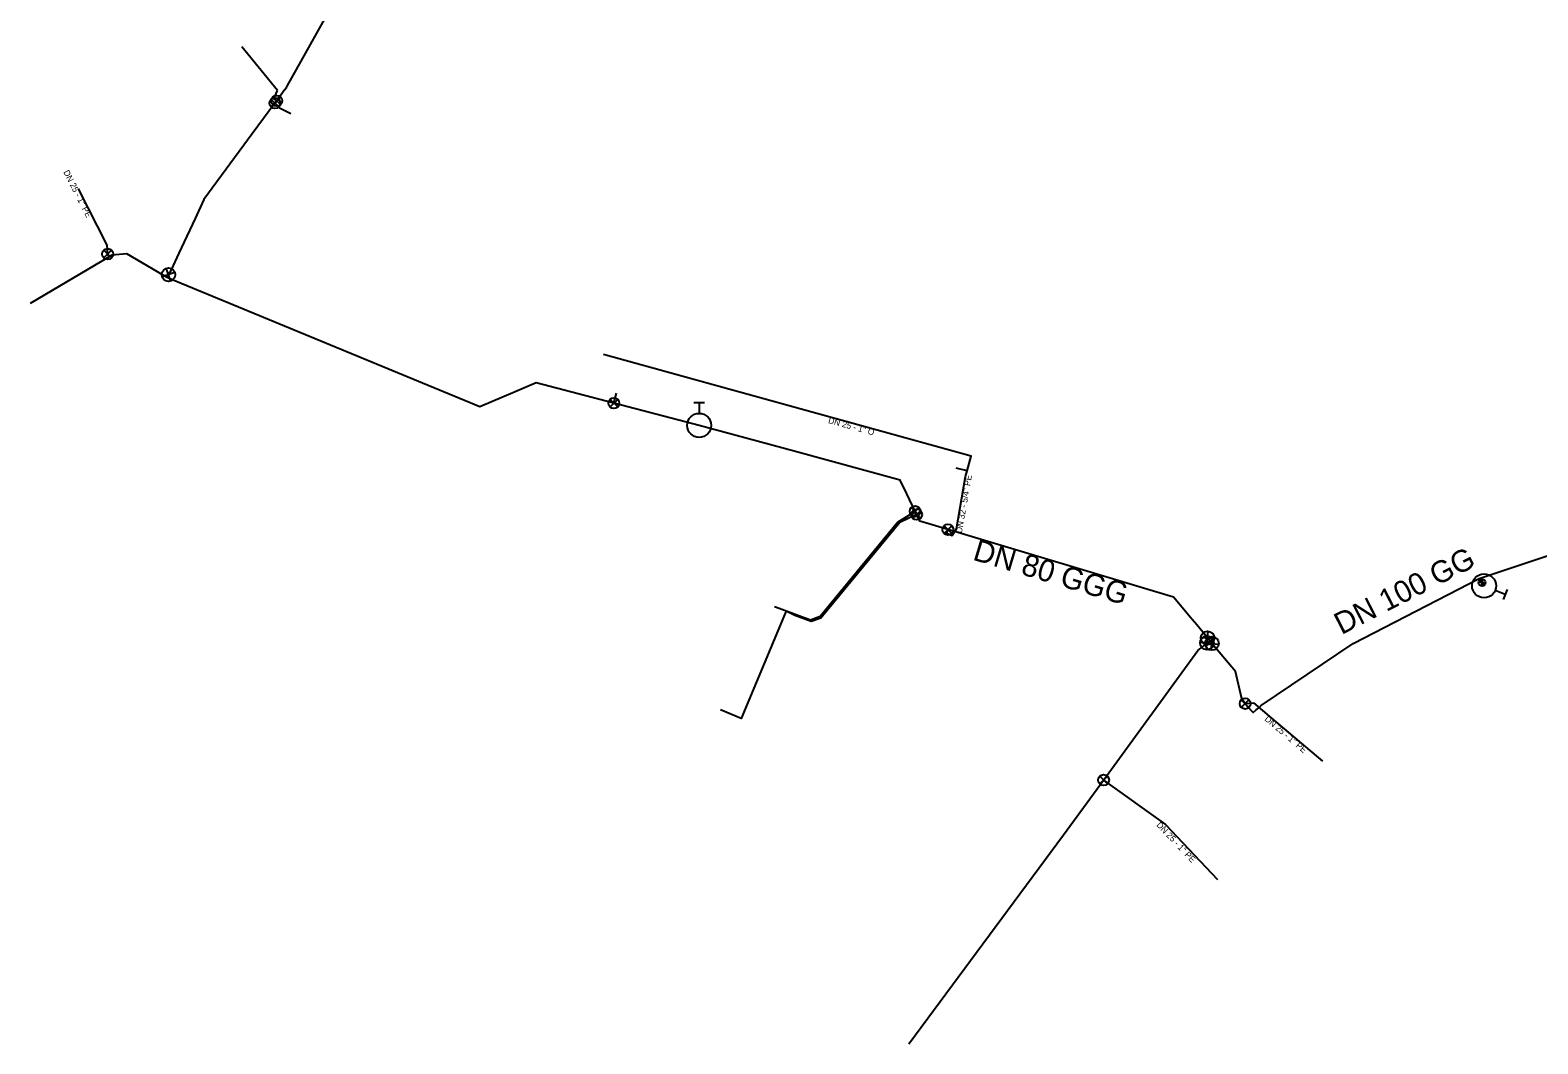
# Model space of a CAD drawing. Extents: x -508836 to -508629, y -1104379 to -1104257.
# Drawn here: x -508836 to -508725.2, y -1104378.9 to -1104304.5 of the extents above; entities that cross this region are included whole.
import ezdxf

# ---------------------------------------------------------------- set-up
doc = ezdxf.new("R2010")
doc.units = 0
for name, color, linetype in [('_hydrantova_odbocka_', 7, 'Continuous'), ('_pripojka_prevzato_z_dokumentace_', 7, 'Continuous'), ('_pripojka_priblizne_', 7, 'Continuous'), ('_voda_smvak_prevzato_z_dokumentace_', 7, 'Continuous'), ('Default', 7, 'Continuous'), ('MoLevel 27', 7, 'Continuous'), ('MoLevel 28', 7, 'Continuous'), ('MoLevel 32', 7, 'Continuous'), ('MoLevel 46', 7, 'Continuous'), ('MoLevel 53', 7, 'Continuous')]:
    doc.layers.add(name, color=color, linetype=linetype)

# ---------------------------------------------------------------- blocks, each defined once
blk = doc.blocks.new('_uzaver_')
at = {"layer": 'Default'}
for p, q in [((-0.000035, -0.000035), (0.000035, 0.000035)), ((0.000035, -0.000035), (-0.000035, 0.000035))]:
    blk.add_line(p, q, dxfattribs=at)
for radius in [0.00005, 0.0000025]:
    blk.add_circle((0, 0), radius, dxfattribs=at)
blk = doc.blocks.new('_uzaver_pripojka_')
at = {"layer": 'Default'}
for p, q in [((-0.000035, -0.000035), (0.000035, 0.000035)), ((0.000035, -0.000035), (-0.000035, 0.000035))]:
    blk.add_line(p, q, dxfattribs=at)
for radius in [0.00005, 0.0000025]:
    blk.add_circle((0, 0), radius, dxfattribs=at)
blk = doc.blocks.new('_hydrant_voda_')
at = {"layer": 'Default'}
for p, q in [((-0.0000225, 0.000095), (0.0000225, 0.000095)), ((0, 0.000095), (0, 0.00005))]:
    blk.add_line(p, q, dxfattribs=at)
blk.add_circle((0, 0), 0.00005, dxfattribs=at)

msp = doc.modelspace()

# ---------------------------------------------------------------- linework, layer by layer
at = {"layer": '_hydrantova_odbocka_'}
msp.add_lwpolyline([(-508729.17, -1104345.29), (-508729.32, -1104345.06), (-508729.52, -1104344.75)], dxfattribs=at)
at = {"layer": '_pripojka_prevzato_z_dokumentace_'}
for p, q in [((-508818.03, -1104309.83), (-508817.69, -1104310.17)), ((-508793.12, -1104331.87), (-508792.93, -1104331.14)), ((-508746.73, -1104353.94), (-508746.11, -1104353.89)), ((-508757.13, -1104359.56), (-508752.58, -1104362.81))]:
    msp.add_line(p, q, dxfattribs=at)
for points in [[(-508817.9, -1104309.66), (-508818.11, -1104309.52), (-508817.84, -1104308.91)], [(-508830.21, -1104321.11), (-508830.32, -1104320.92), (-508830.36, -1104320.26)], [(-508770.98, -1104339.82), (-508772.25, -1104340.62), (-508777.95, -1104347.54), (-508778.66, -1104347.81), (-508780.58, -1104347.11), (-508780.97, -1104346.96), (-508781.32, -1104346.83)], [(-508770.87, -1104340.05), (-508772.1, -1104340.63), (-508777.91, -1104347.67), (-508778.61, -1104347.92), (-508779.81, -1104347.46)], [(-508768.57, -1104341.16), (-508768.68, -1104341.41), (-508768.26, -1104341.6), (-508767.95, -1104341.11)], [(-508779.81, -1104347.46), (-508780.46, -1104347.14), (-508780.5, -1104347.26)]]:
    msp.add_lwpolyline(points, dxfattribs=at)
at = {"layer": '_pripojka_priblizne_'}
for p, q in [((-508817.84, -1104308.91), (-508820.46, -1104305.69)), ((-508817.69, -1104310.17), (-508816.85, -1104310.6)), ((-508830.36, -1104320.26), (-508832.46, -1104316.12)), ((-508767.16, -1104336.84), (-508767.96, -1104336.64)), ((-508746.11, -1104353.89), (-508744.8, -1104355)), ((-508744.8, -1104355), (-508741.05, -1104358.18)), ((-508752.58, -1104362.81), (-508748.75, -1104366.86))]:
    msp.add_line(p, q, dxfattribs=at)
for points in [[(-508767.16, -1104336.84), (-508766.86, -1104335.76), (-508793.88, -1104328.29)], [(-508767.95, -1104341.11), (-508767.28, -1104337.25), (-508767.16, -1104336.84)], [(-508780.5, -1104347.26), (-508783.77, -1104355.03), (-508785.29, -1104354.4)]]:
    msp.add_lwpolyline(points, dxfattribs=at)
at = {"layer": '_voda_smvak_prevzato_z_dokumentace_'}
for p, q in [((-508817.29, -1104308.83), (-508817.59, -1104309.24)), ((-508825.85, -1104322.43), (-508825.95, -1104322.63)), ((-508749.49, -1104349.12), (-508750.29, -1104348.16)), ((-508749.96, -1104349.85), (-508749.54, -1104349.48)), ((-508749.33, -1104349.31), (-508749.54, -1104349.48)), ((-508749.33, -1104349.31), (-508749.49, -1104349.12)), ((-508749.17, -1104349.52), (-508749.33, -1104349.31)), ((-508745.91, -1104354.4), (-508745.73, -1104354.24))]:
    msp.add_line(p, q, dxfattribs=at)
for points in [[(-508817.29, -1104308.83), (-508817.17, -1104308.67), (-508817.13, -1104308.59), (-508813.23, -1104301.6), (-508808.51, -1104289.23), (-508802.59, -1104276.48), (-508791.25, -1104257.48), (-508791.21, -1104257.05)], [(-508729.52, -1104344.75), (-508678.66, -1104327.79), (-508664.54, -1104319.04), (-508649.8, -1104308.07)], [(-508817.59, -1104309.24), (-508817.9, -1104309.66), (-508818.03, -1104309.83), (-508819.69, -1104312.08), (-508823.25, -1104316.9), (-508823.9, -1104318.3), (-508824.69, -1104320.01), (-508825.09, -1104320.85), (-508825.65, -1104322.07), (-508825.85, -1104322.43)], [(-508825.95, -1104322.63), (-508826.25, -1104322.47), (-508828.92, -1104320.89), (-508830.01, -1104320.99), (-508830.21, -1104321.11), (-508836.02, -1104324.56)], [(-508786.85, -1104333.5), (-508793.12, -1104331.87), (-508795.74, -1104331.19), (-508798.84, -1104330.38), (-508800.38, -1104331.04), (-508802.97, -1104332.14), (-508825.64, -1104322.79), (-508825.95, -1104322.63)], [(-508750.63, -1104347.75), (-508751.99, -1104346.12), (-508768.57, -1104341.16), (-508770.64, -1104340.54), (-508770.87, -1104340.05), (-508770.98, -1104339.82), (-508771.59, -1104338.54), (-508772.09, -1104337.52), (-508779.88, -1104335.4), (-508786.85, -1104333.5)], [(-508745.73, -1104354.24), (-508745.54, -1104354.09), (-508738.8, -1104349.52), (-508729.52, -1104344.75)], [(-508750.29, -1104348.16), (-508750.46, -1104347.96), (-508750.63, -1104347.75)], [(-508746.63, -1104354.07), (-508746.73, -1104353.94), (-508746.98, -1104353.6), (-508747.45, -1104351.58), (-508749.17, -1104349.52)], [(-508771.45, -1104378.93), (-508760.07, -1104363.59), (-508757.13, -1104359.56), (-508750.21, -1104350.05), (-508749.96, -1104349.85)], [(-508746.63, -1104354.07), (-508746.14, -1104354.59), (-508745.91, -1104354.4)]]:
    msp.add_lwpolyline(points, dxfattribs=at)

# ---------------------------------------------------------------- block references
at = {"layer": 'MoLevel 27'}
for p, xscale, yscale, rotation in [((-508825.85, -1104322.43), 10000, 9999.999999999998, 64.3726792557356), ((-508729.32, -1104345.06), 5000, 5000.000000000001, 122.782059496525), ((-508749.49, -1104349.12), 10000, 10000, -50.314660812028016), ((-508749.54, -1104349.48), 10000, 10000.000000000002, 42.50883868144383), ((-508749.17, -1104349.52), 10000.000000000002, 9999.999999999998, -50.293442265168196)]:
    msp.add_blockref('_uzaver_', p, dxfattribs=dict(at, xscale=xscale, yscale=yscale, rotation=rotation))
at = {"layer": 'MoLevel 28', "xscale": 17636.68430335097, "yscale": 17636.68430335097}
msp.add_blockref('_hydrant_voda_', (-508786.85, -1104333.5), dxfattribs=at)
at = {"layer": 'MoLevel 28', "xscale": 17636.68430335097, "yscale": 17636.68430335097, "rotation": -112.08110277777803}
msp.add_blockref('_hydrant_voda_', (-508729.17, -1104345.29), dxfattribs=at)
at = {"layer": 'MoLevel 53', "xscale": 7999.999999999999, "yscale": 7999.999999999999}
for p in [(-508818.03, -1104309.83), (-508817.9, -1104309.66), (-508830.32, -1104320.92), (-508793.12, -1104331.87), (-508770.98, -1104339.82), (-508770.87, -1104340.05), (-508768.57, -1104341.16), (-508746.73, -1104353.94), (-508757.13, -1104359.56)]:
    msp.add_blockref('_uzaver_pripojka_', p, dxfattribs=at)

# ---------------------------------------------------------------- texts
at = {"layer": 'MoLevel 32'}
for s, rotation, p in [("DN 25 - 1'' PE", 296.8632, (-508833.59, -1104314.89)), ("DN 25 - 1'' O", 344.5467, (-508777.4, -1104333.32)), ("DN 32 - 5/4'' PE", 80.0999, (-508767.55, -1104341.44)), ("DN 25 - 1'' PE", 319.6815, (-508745.34, -1104355.14)), ("DN 25 - 1'' PE", 313.4079, (-508753.28, -1104362.89))]:
    msp.add_text(s, height=0.455, rotation=rotation, dxfattribs=at).set_placement(p)
at = {"layer": 'MoLevel 46'}
for s, rotation, p in [('DN 80 GGG', 343.3452, (-508766.82, -1104343.36)), ('DN 100 GG', 27.1819, (-508739.65, -1104348.91))]:
    msp.add_text(s, height=1.605, rotation=rotation, dxfattribs=at).set_placement(p)

doc.saveas('drawing.dxf')
